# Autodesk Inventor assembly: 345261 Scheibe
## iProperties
Company: Mayer & Müller AG
Created: 2006-07
Part Number: 345261 Scheibe
Document SubType Name: Weldment
Designer: I.Baliuc
Material: Geschweißt
Description: Schaltscheibenhebel
Cost Center: 0,424 kg
Authority: 53902 mm^3
Mass: 423.657 g
Surface Area: 131.517 cm^2
Volume: 53.9004 cm^3
Density: 7.86 g/cm^3
Zweck: Vorkontakt HSLT
SaveDate: 2006-10-25
SaveTime: 22:20
TotalMass: 0,424 kg
TotalVolume: 53902 mm^3
Author: T.Messerschmitt
Revision Number: 345261
